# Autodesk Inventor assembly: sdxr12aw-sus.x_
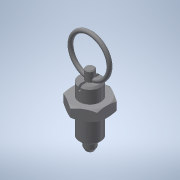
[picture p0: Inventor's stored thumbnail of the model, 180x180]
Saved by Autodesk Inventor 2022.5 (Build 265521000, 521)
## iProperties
Part Number: sdxr12aw-sus.x_
Material: 一般
Document SubType Name: Assembly
Designer: ImaoCorp
Sending System: SOLIDWORKS 2017-2017317
MC: AMD64
MC_MODEL: Intel64 Family 6 Model 60 Stepping 3, GenuineIntel
OS: Windows_NT
FRU: Parasolid Version 29.0, build 201,  4-17-2017
FORMAT: text
GUISE: transmit
KEY: sdxr12aw-sus
FILE: sdxr12aw-sus.x_t
DATE: Wed Sep 18 16:15:44 2019
Author: ImaoCorp
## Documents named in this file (3)
- X:\14_SW2022-Inv2022\00_全2023-1023新製品(TCC)まで\s\sdxr12aw-sus\SDXR12AW-SUS.iam
- X:\14_SW2022-Inv2022\00_全2023-1023新製品(TCC)まで\s\sdxr12aw-sus\sdxr12aw-sus_01.ipt
- X:\14_SW2022-Inv2022\00_全2023-1023新製品(TCC)まで\s\sdxr12aw-sus\sdxr12aw-sus_02.ipt
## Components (2 placed, 2 different names)
1. sdxr12aw-sus_01
2. sdxr12aw-sus_02
